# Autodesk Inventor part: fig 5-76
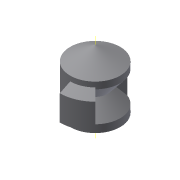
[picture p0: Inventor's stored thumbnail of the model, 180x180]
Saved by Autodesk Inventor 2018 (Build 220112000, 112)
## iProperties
Created: 2004-05
Part Number: fig 5-76
Document SubType Name: Modeling
Designer: CADCIM Technologies
Manufacturer: Standard
Standards Organization: Custom
Density: 1 g/cm^3
Material: Generic
Appearance: Default
Author: CADCIM Technologies
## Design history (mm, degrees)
sketch "Sketch1"
  geometry: L1 (0, -21.51)-(0, 21.51); L2 (0, 21.51)-(-14.639, 13.059); L3 (-14.639, 13.059)-(-14.639, -13.059); L4 (-14.639, -13.059)-(0, -21.51); 2 further points
  constraints: 8 end point, 1 coincident, 1 equal length, 1 midpoint, 1 parallel, 1 vertical, 1 other
  dimensions: "d3" = 120 deg angle of L4 L3
revolve "Revolution1" sketch "Sketch1" stored, may be unused: angle "d0" = 90 deg
workaxis "Work Axis1"
sketch "Sketch2"
  geometry: L1 (-15.658, 10.423)-(-7.144, 0); L2 (-7.144, 0)-(-15.658, -9.738); L3 (-15.658, -9.738)-(-15.658, 10.423); L4 (0, -25.812)-(0, 34.416) reference
  constraints: 6 end point, 1 vertical
revolve "Revolution2" sketch "Sketch2" stored, may be unused: angle "d4" = 140 deg
sketch "Sketch3"
  geometry: L1 (-14.955, 9.983)-(-20.736, 7.191); L2 (-20.736, 7.191)-(-20.736, -7.686); L3 (-20.736, -7.686)-(-15, -10.57); L4 (0, -25.812)-(0, 34.416) reference
  constraints: 6 end point, 1 equal length, 1 vertical
revolve "Revolution4" sketch "Sketch3" stored, may be unused: angle "d9" = 45 deg
body "Solid1"
other parameters: "d10" = 45 deg
